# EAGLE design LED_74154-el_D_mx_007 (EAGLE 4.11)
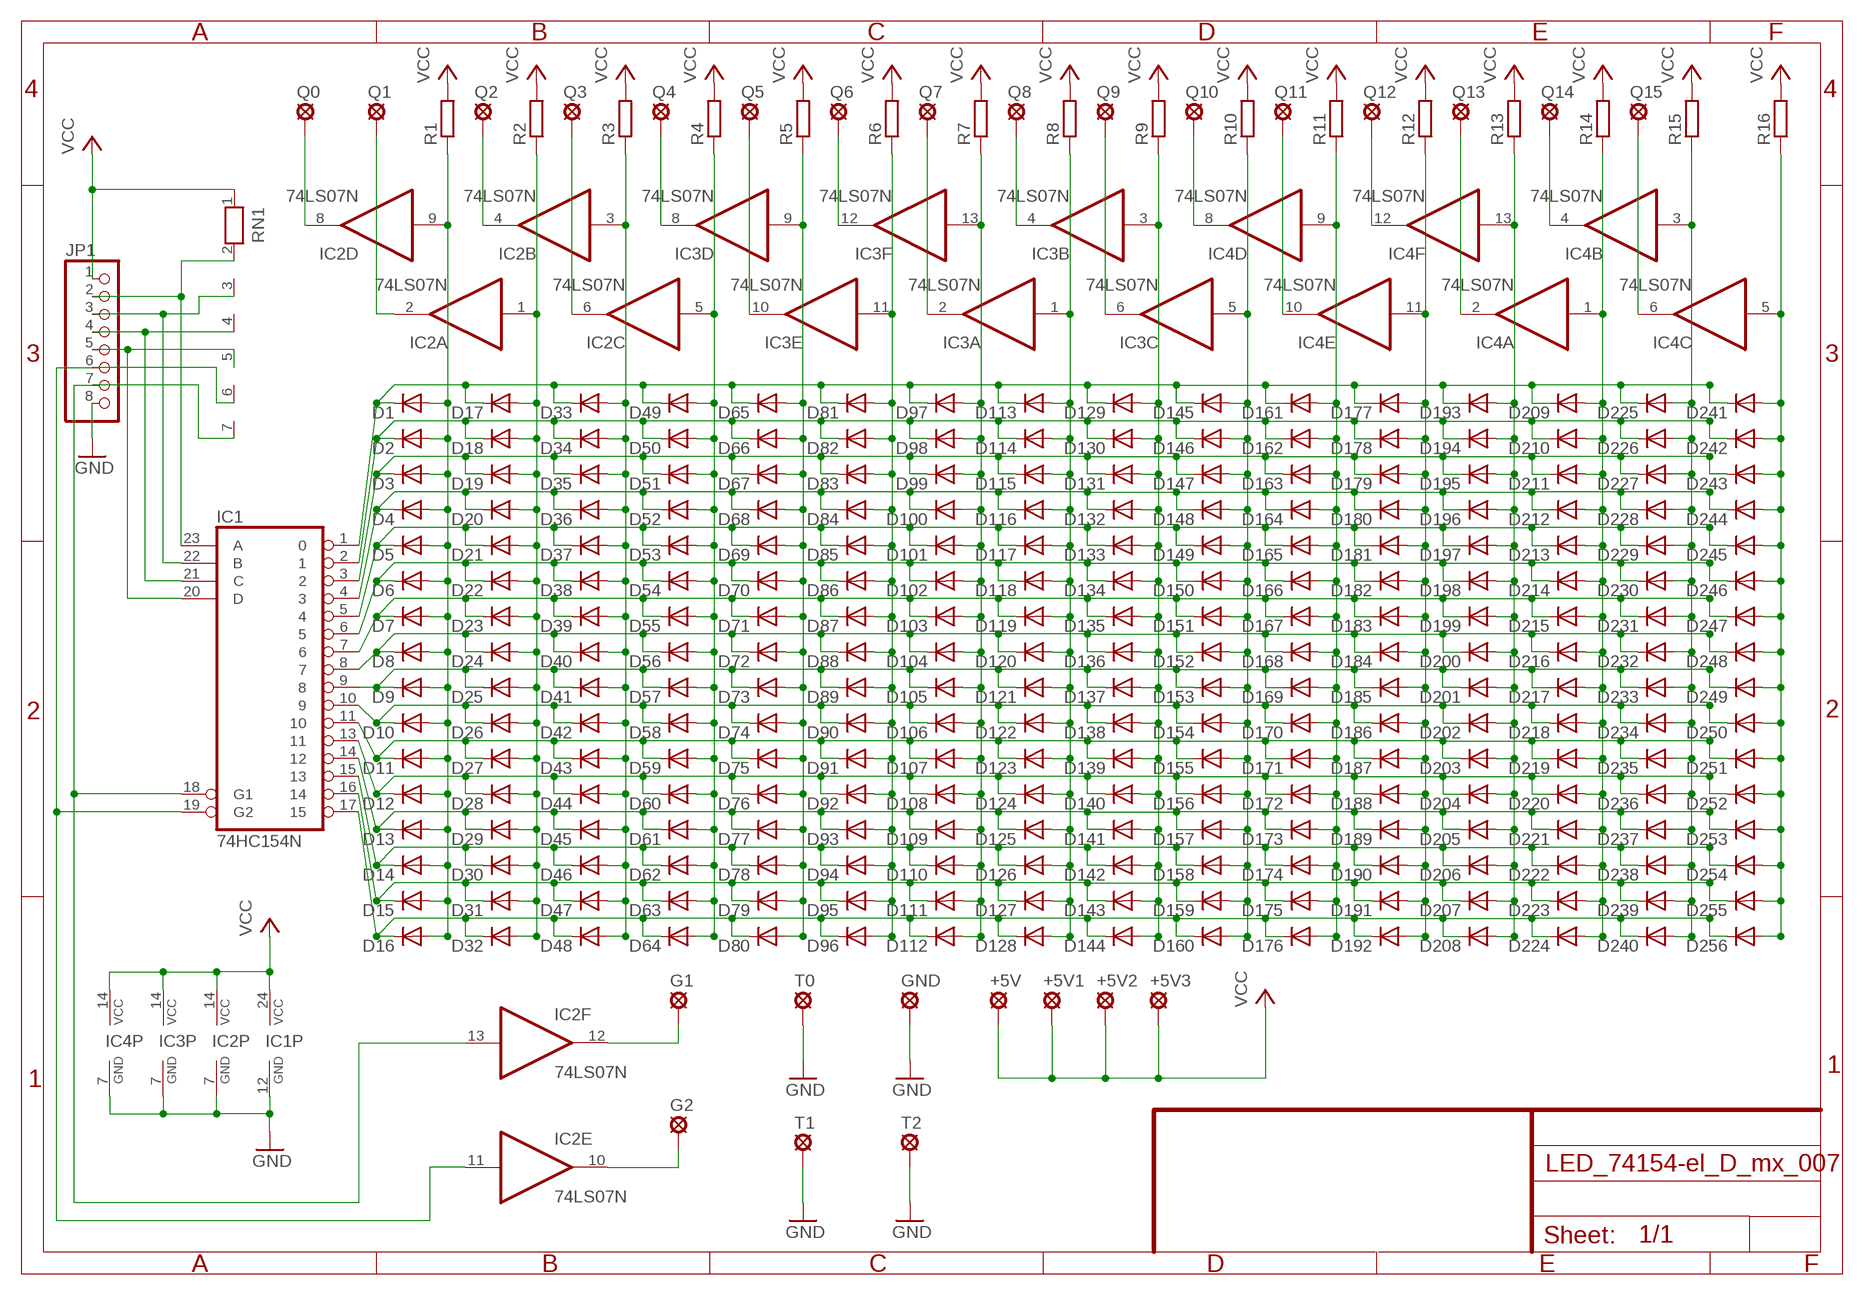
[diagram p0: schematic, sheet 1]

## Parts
+5V  SE11  [SE11]
+5V1  SE11  [SE11]
+5V2  SE11  [SE11]
+5V3  SE11  [SE11]
D1  DIODE-D-2.5  [D-2.5]
D2  DIODE-D-2.5  [D-2.5]
D3  DIODE-D-2.5  [D-2.5]
D4  DIODE-D-2.5  [D-2.5]
D5  DIODE-D-2.5  [D-2.5]
D6  DIODE-D-2.5  [D-2.5]
D7  DIODE-D-2.5  [D-2.5]
D8  DIODE-D-2.5  [D-2.5]
D9  DIODE-D-2.5  [D-2.5]
D10  DIODE-D-2.5  [D-2.5]
D11  DIODE-D-2.5  [D-2.5]
D12  DIODE-D-2.5  [D-2.5]
D13  DIODE-D-2.5  [D-2.5]
D14  DIODE-D-2.5  [D-2.5]
D15  DIODE-D-2.5  [D-2.5]
D16  DIODE-D-2.5  [D-2.5]
D17  DIODE-D-2.5  [D-2.5]
D18  DIODE-D-2.5  [D-2.5]
D19  DIODE-D-2.5  [D-2.5]
D20  DIODE-D-2.5  [D-2.5]
D21  DIODE-D-2.5  [D-2.5]
D22  DIODE-D-2.5  [D-2.5]
D23  DIODE-D-2.5  [D-2.5]
D24  DIODE-D-2.5  [D-2.5]
D25  DIODE-D-2.5  [D-2.5]
D26  DIODE-D-2.5  [D-2.5]
D27  DIODE-D-2.5  [D-2.5]
D28  DIODE-D-2.5  [D-2.5]
D29  DIODE-D-2.5  [D-2.5]
D30  DIODE-D-2.5  [D-2.5]
D31  DIODE-D-2.5  [D-2.5]
D32  DIODE-D-2.5  [D-2.5]
D33  DIODE-D-2.5  [D-2.5]
D34  DIODE-D-2.5  [D-2.5]
D35  DIODE-D-2.5  [D-2.5]
D36  DIODE-D-2.5  [D-2.5]
D37  DIODE-D-2.5  [D-2.5]
D38  DIODE-D-2.5  [D-2.5]
D39  DIODE-D-2.5  [D-2.5]
D40  DIODE-D-2.5  [D-2.5]
D41  DIODE-D-2.5  [D-2.5]
D42  DIODE-D-2.5  [D-2.5]
D43  DIODE-D-2.5  [D-2.5]
D44  DIODE-D-2.5  [D-2.5]
D45  DIODE-D-2.5  [D-2.5]
D46  DIODE-D-2.5  [D-2.5]
D47  DIODE-D-2.5  [D-2.5]
D48  DIODE-D-2.5  [D-2.5]
D49  DIODE-D-2.5  [D-2.5]
D50  DIODE-D-2.5  [D-2.5]
D51  DIODE-D-2.5  [D-2.5]
D52  DIODE-D-2.5  [D-2.5]
D53  DIODE-D-2.5  [D-2.5]
D54  DIODE-D-2.5  [D-2.5]
D55  DIODE-D-2.5  [D-2.5]
D56  DIODE-D-2.5  [D-2.5]
D57  DIODE-D-2.5  [D-2.5]
D58  DIODE-D-2.5  [D-2.5]
D59  DIODE-D-2.5  [D-2.5]
D60  DIODE-D-2.5  [D-2.5]
D61  DIODE-D-2.5  [D-2.5]
D62  DIODE-D-2.5  [D-2.5]
D63  DIODE-D-2.5  [D-2.5]
D64  DIODE-D-2.5  [D-2.5]
D65  DIODE-D-2.5  [D-2.5]
D66  DIODE-D-2.5  [D-2.5]
D67  DIODE-D-2.5  [D-2.5]
D68  DIODE-D-2.5  [D-2.5]
D69  DIODE-D-2.5  [D-2.5]
D70  DIODE-D-2.5  [D-2.5]
D71  DIODE-D-2.5  [D-2.5]
D72  DIODE-D-2.5  [D-2.5]
D73  DIODE-D-2.5  [D-2.5]
D74  DIODE-D-2.5  [D-2.5]
D75  DIODE-D-2.5  [D-2.5]
D76  DIODE-D-2.5  [D-2.5]
D77  DIODE-D-2.5  [D-2.5]
D78  DIODE-D-2.5  [D-2.5]
D79  DIODE-D-2.5  [D-2.5]
D80  DIODE-D-2.5  [D-2.5]
D81  DIODE-D-2.5  [D-2.5]
D82  DIODE-D-2.5  [D-2.5]
D83  DIODE-D-2.5  [D-2.5]
D84  DIODE-D-2.5  [D-2.5]
D85  DIODE-D-2.5  [D-2.5]
D86  DIODE-D-2.5  [D-2.5]
D87  DIODE-D-2.5  [D-2.5]
D88  DIODE-D-2.5  [D-2.5]
D89  DIODE-D-2.5  [D-2.5]
D90  DIODE-D-2.5  [D-2.5]
D91  DIODE-D-2.5  [D-2.5]
D92  DIODE-D-2.5  [D-2.5]
D93  DIODE-D-2.5  [D-2.5]
D94  DIODE-D-2.5  [D-2.5]
D95  DIODE-D-2.5  [D-2.5]
D96  DIODE-D-2.5  [D-2.5]
D97  DIODE-D-2.5  [D-2.5]
D98  DIODE-D-2.5  [D-2.5]
D99  DIODE-D-2.5  [D-2.5]
D100  DIODE-D-2.5  [D-2.5]
D101  DIODE-D-2.5  [D-2.5]
D102  DIODE-D-2.5  [D-2.5]
D103  DIODE-D-2.5  [D-2.5]
D104  DIODE-D-2.5  [D-2.5]
D105  DIODE-D-2.5  [D-2.5]
D106  DIODE-D-2.5  [D-2.5]
D107  DIODE-D-2.5  [D-2.5]
D108  DIODE-D-2.5  [D-2.5]
D109  DIODE-D-2.5  [D-2.5]
D110  DIODE-D-2.5  [D-2.5]
D111  DIODE-D-2.5  [D-2.5]
D112  DIODE-D-2.5  [D-2.5]
D113  DIODE-D-2.5  [D-2.5]
D114  DIODE-D-2.5  [D-2.5]
D115  DIODE-D-2.5  [D-2.5]
D116  DIODE-D-2.5  [D-2.5]
D117  DIODE-D-2.5  [D-2.5]
D118  DIODE-D-2.5  [D-2.5]
D119  DIODE-D-2.5  [D-2.5]
D120  DIODE-D-2.5  [D-2.5]
D121  DIODE-D-2.5  [D-2.5]
D122  DIODE-D-2.5  [D-2.5]
D123  DIODE-D-2.5  [D-2.5]
D124  DIODE-D-2.5  [D-2.5]
D125  DIODE-D-2.5  [D-2.5]
D126  DIODE-D-2.5  [D-2.5]
D127  DIODE-D-2.5  [D-2.5]
D128  DIODE-D-2.5  [D-2.5]
D129  DIODE-D-2.5  [D-2.5]
D130  DIODE-D-2.5  [D-2.5]
D131  DIODE-D-2.5  [D-2.5]
D132  DIODE-D-2.5  [D-2.5]
D133  DIODE-D-2.5  [D-2.5]
D134  DIODE-D-2.5  [D-2.5]
D135  DIODE-D-2.5  [D-2.5]
D136  DIODE-D-2.5  [D-2.5]
D137  DIODE-D-2.5  [D-2.5]
D138  DIODE-D-2.5  [D-2.5]
D139  DIODE-D-2.5  [D-2.5]
D140  DIODE-D-2.5  [D-2.5]
D141  DIODE-D-2.5  [D-2.5]
D142  DIODE-D-2.5  [D-2.5]
D143  DIODE-D-2.5  [D-2.5]
D144  DIODE-D-2.5  [D-2.5]
D145  DIODE-D-2.5  [D-2.5]
D146  DIODE-D-2.5  [D-2.5]
D147  DIODE-D-2.5  [D-2.5]
D148  DIODE-D-2.5  [D-2.5]
D149  DIODE-D-2.5  [D-2.5]
D150  DIODE-D-2.5  [D-2.5]
D151  DIODE-D-2.5  [D-2.5]
D152  DIODE-D-2.5  [D-2.5]
D153  DIODE-D-2.5  [D-2.5]
D154  DIODE-D-2.5  [D-2.5]
D155  DIODE-D-2.5  [D-2.5]
D156  DIODE-D-2.5  [D-2.5]
D157  DIODE-D-2.5  [D-2.5]
D158  DIODE-D-2.5  [D-2.5]
D159  DIODE-D-2.5  [D-2.5]
D160  DIODE-D-2.5  [D-2.5]
D161  DIODE-D-2.5  [D-2.5]
D162  DIODE-D-2.5  [D-2.5]
D163  DIODE-D-2.5  [D-2.5]
D164  DIODE-D-2.5  [D-2.5]
D165  DIODE-D-2.5  [D-2.5]
D166  DIODE-D-2.5  [D-2.5]
D167  DIODE-D-2.5  [D-2.5]
D168  DIODE-D-2.5  [D-2.5]
D169  DIODE-D-2.5  [D-2.5]
D170  DIODE-D-2.5  [D-2.5]
D171  DIODE-D-2.5  [D-2.5]
D172  DIODE-D-2.5  [D-2.5]
D173  DIODE-D-2.5  [D-2.5]
D174  DIODE-D-2.5  [D-2.5]
D175  DIODE-D-2.5  [D-2.5]
D176  DIODE-D-2.5  [D-2.5]
D177  DIODE-D-2.5  [D-2.5]
D178  DIODE-D-2.5  [D-2.5]
D179  DIODE-D-2.5  [D-2.5]
D180  DIODE-D-2.5  [D-2.5]
D181  DIODE-D-2.5  [D-2.5]
D182  DIODE-D-2.5  [D-2.5]
D183  DIODE-D-2.5  [D-2.5]
D184  DIODE-D-2.5  [D-2.5]
D185  DIODE-D-2.5  [D-2.5]
D186  DIODE-D-2.5  [D-2.5]
D187  DIODE-D-2.5  [D-2.5]
D188  DIODE-D-2.5  [D-2.5]
D189  DIODE-D-2.5  [D-2.5]
D190  DIODE-D-2.5  [D-2.5]
D191  DIODE-D-2.5  [D-2.5]
D192  DIODE-D-2.5  [D-2.5]
D193  DIODE-D-2.5  [D-2.5]
D194  DIODE-D-2.5  [D-2.5]
D195  DIODE-D-2.5  [D-2.5]
D196  DIODE-D-2.5  [D-2.5]
D197  DIODE-D-2.5  [D-2.5]
D198  DIODE-D-2.5  [D-2.5]
D199  DIODE-D-2.5  [D-2.5]
D200  DIODE-D-2.5  [D-2.5]
D201  DIODE-D-2.5  [D-2.5]
D202  DIODE-D-2.5  [D-2.5]
D203  DIODE-D-2.5  [D-2.5]
D204  DIODE-D-2.5  [D-2.5]
D205  DIODE-D-2.5  [D-2.5]
D206  DIODE-D-2.5  [D-2.5]
D207  DIODE-D-2.5  [D-2.5]
D208  DIODE-D-2.5  [D-2.5]
D209  DIODE-D-2.5  [D-2.5]
D210  DIODE-D-2.5  [D-2.5]
D211  DIODE-D-2.5  [D-2.5]
D212  DIODE-D-2.5  [D-2.5]
D213  DIODE-D-2.5  [D-2.5]
D214  DIODE-D-2.5  [D-2.5]
D215  DIODE-D-2.5  [D-2.5]
D216  DIODE-D-2.5  [D-2.5]
D217  DIODE-D-2.5  [D-2.5]
D218  DIODE-D-2.5  [D-2.5]
D219  DIODE-D-2.5  [D-2.5]
D220  DIODE-D-2.5  [D-2.5]
D221  DIODE-D-2.5  [D-2.5]
D222  DIODE-D-2.5  [D-2.5]
D223  DIODE-D-2.5  [D-2.5]
D224  DIODE-D-2.5  [D-2.5]
D225  DIODE-D-2.5  [D-2.5]
D226  DIODE-D-2.5  [D-2.5]
D227  DIODE-D-2.5  [D-2.5]
D228  DIODE-D-2.5  [D-2.5]
D229  DIODE-D-2.5  [D-2.5]
D230  DIODE-D-2.5  [D-2.5]
D231  DIODE-D-2.5  [D-2.5]
D232  DIODE-D-2.5  [D-2.5]
D233  DIODE-D-2.5  [D-2.5]
D234  DIODE-D-2.5  [D-2.5]
D235  DIODE-D-2.5  [D-2.5]
D236  DIODE-D-2.5  [D-2.5]
D237  DIODE-D-2.5  [D-2.5]
D238  DIODE-D-2.5  [D-2.5]
D239  DIODE-D-2.5  [D-2.5]
D240  DIODE-D-2.5  [D-2.5]
D241  DIODE-D-2.5  [D-2.5]
D242  DIODE-D-2.5  [D-2.5]
D243  DIODE-D-2.5  [D-2.5]
D244  DIODE-D-2.5  [D-2.5]
D245  DIODE-D-2.5  [D-2.5]
D246  DIODE-D-2.5  [D-2.5]
D247  DIODE-D-2.5  [D-2.5]
D248  DIODE-D-2.5  [D-2.5]
D249  DIODE-D-2.5  [D-2.5]
D250  DIODE-D-2.5  [D-2.5]
D251  DIODE-D-2.5  [D-2.5]
D252  DIODE-D-2.5  [D-2.5]
D253  DIODE-D-2.5  [D-2.5]
D254  DIODE-D-2.5  [D-2.5]
D255  DIODE-D-2.5  [D-2.5]
D256  DIODE-D-2.5  [D-2.5]
G1  SE11  [SE11]
G2  SE11  [SE11]
GND  SE11  [SE11]
IC1  74HC154N  [DIL24-6]
IC2  74LS07N  [DIL14]
IC3  74LS07N  [DIL14]
IC4  74LS07N  [DIL14]
JP1  PINHD-1X8  [1X08]
Q0  SE11  [SE11]
Q1  SE11  [SE11]
Q2  SE11  [SE11]
Q3  SE11  [SE11]
Q4  SE11  [SE11]
Q5  SE11  [SE11]
Q6  SE11  [SE11]
Q7  SE11  [SE11]
Q8  SE11  [SE11]
Q9  SE11  [SE11]
Q10  SE11  [SE11]
Q11  SE11  [SE11]
Q12  SE11  [SE11]
Q13  SE11  [SE11]
Q14  SE11  [SE11]
Q15  SE11  [SE11]
R1  R-EU_0204/5  [0204/5]
R2  R-EU_0204/5  [0204/5]
R3  R-EU_0204/5  [0204/5]
R4  R-EU_0204/5  [0204/5]
R5  R-EU_0204/5  [0204/5]
R6  R-EU_0204/5  [0204/5]
R7  R-EU_0204/5  [0204/5]
R8  R-EU_0204/5  [0204/5]
R9  R-EU_0204/5  [0204/5]
R10  R-EU_0204/5  [0204/5]
R11  R-EU_0204/5  [0204/5]
R12  R-EU_0204/5  [0204/5]
R13  R-EU_0204/5  [0204/5]
R14  R-EU_0204/5  [0204/5]
R15  R-EU_0204/5  [0204/5]
R16  R-EU_0204/5  [0204/5]
RN1  RN06  [RN-7]
T0  SE11  [SE11]
T1  SE11  [SE11]
T2  SE11  [SE11]

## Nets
GND: GND.MP IC1.12(GND) IC2.7(P:GND) IC3.7(P:GND) IC4.7(P:GND) JP1.8 T0.MP T1.MP T2.MP
N$1: D225.A D226.A D227.A D228.A D229.A D230.A D231.A D232.A D233.A D234.A D235.A D236.A D237.A D238.A D239.A D240.A IC4.3(B:I) R15.1
N$2: D2.C D18.C D34.C D50.C D66.C D82.C D98.C D114.C D130.C D146.C D162.C D178.C D194.C D210.C D226.C D242.C IC1.2
N$3: D33.A D34.A D35.A D36.A D37.A D38.A D39.A D40.A D41.A D42.A D43.A D44.A D45.A D46.A D47.A D48.A IC2.3(B:I) R3.1
N$4: D4.C D20.C D36.C D52.C D68.C D84.C D100.C D116.C D132.C D148.C D164.C D180.C D196.C D212.C D228.C D244.C IC1.4
N$5: D5.C D21.C D37.C D53.C D69.C D85.C D101.C D117.C D133.C D149.C D165.C D181.C D197.C D213.C D229.C D245.C IC1.5
N$6: D6.C D22.C D38.C D54.C D70.C D86.C D102.C D118.C D134.C D150.C D166.C D182.C D198.C D214.C D230.C D246.C IC1.6
N$7: D7.C D23.C D39.C D55.C D71.C D87.C D103.C D119.C D135.C D151.C D167.C D183.C D199.C D215.C D231.C D247.C IC1.7
N$8: D8.C D24.C D40.C D56.C D72.C D88.C D104.C D120.C D136.C D152.C D168.C D184.C D200.C D216.C D232.C D248.C IC1.8
N$9: D9.C D25.C D41.C D57.C D73.C D89.C D105.C D121.C D137.C D153.C D169.C D185.C D201.C D217.C D233.C D249.C IC1.9
N$10: D10.C D26.C D42.C D58.C D74.C D90.C D106.C D122.C D138.C D154.C D170.C D186.C D202.C D218.C D234.C D250.C IC1.10
N$11: D11.C D27.C D43.C D59.C D75.C D91.C D107.C D123.C D139.C D155.C D171.C D187.C D203.C D219.C D235.C D251.C IC1.11
N$12: D12.C D28.C D44.C D60.C D76.C D92.C D108.C D124.C D140.C D156.C D172.C D188.C D204.C D220.C D236.C D252.C IC1.13
N$13: D13.C D29.C D45.C D61.C D77.C D93.C D109.C D125.C D141.C D157.C D173.C D189.C D205.C D221.C D237.C D253.C IC1.14
N$14: D14.C D30.C D46.C D62.C D78.C D94.C D110.C D126.C D142.C D158.C D174.C D190.C D206.C D222.C D238.C D254.C IC1.15
N$15: D15.C D31.C D47.C D63.C D79.C D95.C D111.C D127.C D143.C D159.C D175.C D191.C D207.C D223.C D239.C D255.C IC1.16
N$16: D16.C D32.C D48.C D64.C D80.C D96.C D112.C D128.C D144.C D160.C D176.C D192.C D208.C D224.C D240.C D256.C IC1.17
N$17: D49.A D50.A D51.A D52.A D53.A D54.A D55.A D56.A D57.A D58.A D59.A D60.A D61.A D62.A D63.A D64.A IC2.5(C:I) R4.1
N$18: D65.A D66.A D67.A D68.A D69.A D70.A D71.A D72.A D73.A D74.A D75.A D76.A D77.A D78.A D79.A D80.A IC3.9(D:I) R5.1
N$19: D81.A D82.A D83.A D84.A D85.A D86.A D87.A D88.A D89.A D90.A D91.A D92.A D93.A D94.A D95.A D96.A IC3.11(E:I) R6.1
N$20: D97.A D98.A D99.A D100.A D101.A D102.A D103.A D104.A D105.A D106.A D107.A D108.A D109.A D110.A D111.A D112.A IC3.13(F:I) R7.1
N$21: D3.C D19.C D35.C D51.C D67.C D83.C D99.C D115.C D131.C D147.C D163.C D179.C D195.C D211.C D227.C D243.C IC1.3
N$22: IC1.19(G2) IC2.11(E:I) JP1.6 RN1.6
N$23: IC1.18(G1) IC2.13(F:I) JP1.7 RN1.7
N$24: D145.A D146.A D147.A D148.A D149.A D150.A D151.A D152.A D153.A D154.A D155.A D156.A D157.A D158.A D159.A D160.A IC3.5(C:I) R10.1
N$25: D193.A D194.A D195.A D196.A D197.A D198.A D199.A D200.A D201.A D202.A D203.A D204.A D205.A D206.A D207.A D208.A IC4.13(F:I) R13.1
N$26: IC1.23(A) JP1.2 RN1.2
N$27: IC1.22(B) JP1.3 RN1.3
N$28: IC1.21(C) JP1.4 RN1.4
N$29: D1.A D2.A D3.A D4.A D5.A D6.A D7.A D8.A D9.A D10.A D11.A D12.A D13.A D14.A D15.A D16.A IC2.9(D:I) R1.1
N$30: D17.A D18.A D19.A D20.A D21.A D22.A D23.A D24.A D25.A D26.A D27.A D28.A D29.A D30.A D31.A D32.A IC2.1(A:I) R2.1
N$31: IC1.20(D) JP1.5 RN1.5
N$32: D113.A D114.A D115.A D116.A D117.A D118.A D119.A D120.A D121.A D122.A D123.A D124.A D125.A D126.A D127.A D128.A IC3.1(A:I) R8.1
N$33: D129.A D130.A D131.A D132.A D133.A D134.A D135.A D136.A D137.A D138.A D139.A D140.A D141.A D142.A D143.A D144.A IC3.3(B:I) R9.1
N$34: D241.A D242.A D243.A D244.A D245.A D246.A D247.A D248.A D249.A D250.A D251.A D252.A D253.A D254.A D255.A D256.A IC4.5(C:I) R16.1
N$39: D209.A D210.A D211.A D212.A D213.A D214.A D215.A D216.A D217.A D218.A D219.A D220.A D221.A D222.A D223.A D224.A IC4.1(A:I) R14.1
N$41: D161.A D162.A D163.A D164.A D165.A D166.A D167.A D168.A D169.A D170.A D171.A D172.A D173.A D174.A D175.A D176.A IC4.9(D:I) R11.1
N$42: D1.C D17.C D33.C D49.C D65.C D81.C D97.C D113.C D129.C D145.C D161.C D177.C D193.C D209.C D225.C D241.C IC1.1
N$50: D177.A D178.A D179.A D180.A D181.A D182.A D183.A D184.A D185.A D186.A D187.A D188.A D189.A D190.A D191.A D192.A IC4.11(E:I) R12.1
N$51: G1.MP IC2.12(F:O)
N$52: IC2.8(D:O) Q0.MP
N$53: IC2.2(A:O) Q1.MP
N$54: IC2.4(B:O) Q2.MP
N$55: IC2.6(C:O) Q3.MP
N$56: IC3.8(D:O) Q4.MP
N$57: IC3.10(E:O) Q5.MP
N$58: IC3.12(F:O) Q6.MP
N$59: IC3.2(A:O) Q7.MP
N$60: IC3.4(B:O) Q8.MP
N$61: IC3.6(C:O) Q9.MP
N$62: IC4.8(D:O) Q10.MP
N$63: IC4.10(E:O) Q11.MP
N$64: IC4.12(F:O) Q12.MP
N$65: IC4.2(A:O) Q13.MP
N$66: IC4.4(B:O) Q14.MP
N$67: IC4.6(C:O) Q15.MP
N$68: G2.MP IC2.10(E:O)
VCC: +5V1.MP +5V2.MP +5V3.MP +5V.MP IC1.24(VCC) IC2.14(P:VCC) IC3.14(P:VCC) IC4.14(P:VCC) JP1.1 R1.2 R2.2 R3.2 R4.2 R5.2 R6.2 R7.2 R8.2 R9.2 R10.2 R11.2 R12.2 R13.2 R14.2 R15.2 R16.2 RN1.1

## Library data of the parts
+5V +5V1-+5V3 G1 G2 GND Q0 Q1-Q15 T0 T1 T2 = solpad:SE11: SOLDER PAD
D1-D256 = diode:DIODE-: DIODE
IC1 = 74xx-eu:74*154: 4-line to 16-line data SELECTOR/MULTIPLEXER
IC2-IC4 = 74xx-eu:74*07: Hex BUFFER, open collector high-voltage output
JP1 = pinhead:PINHD-1X8: PIN HEADER
R1-R16 = rcl:R-EU_: RESISTOR, European symbol
RN1 = resistor-net:RN06: RESISTOR NETWORK

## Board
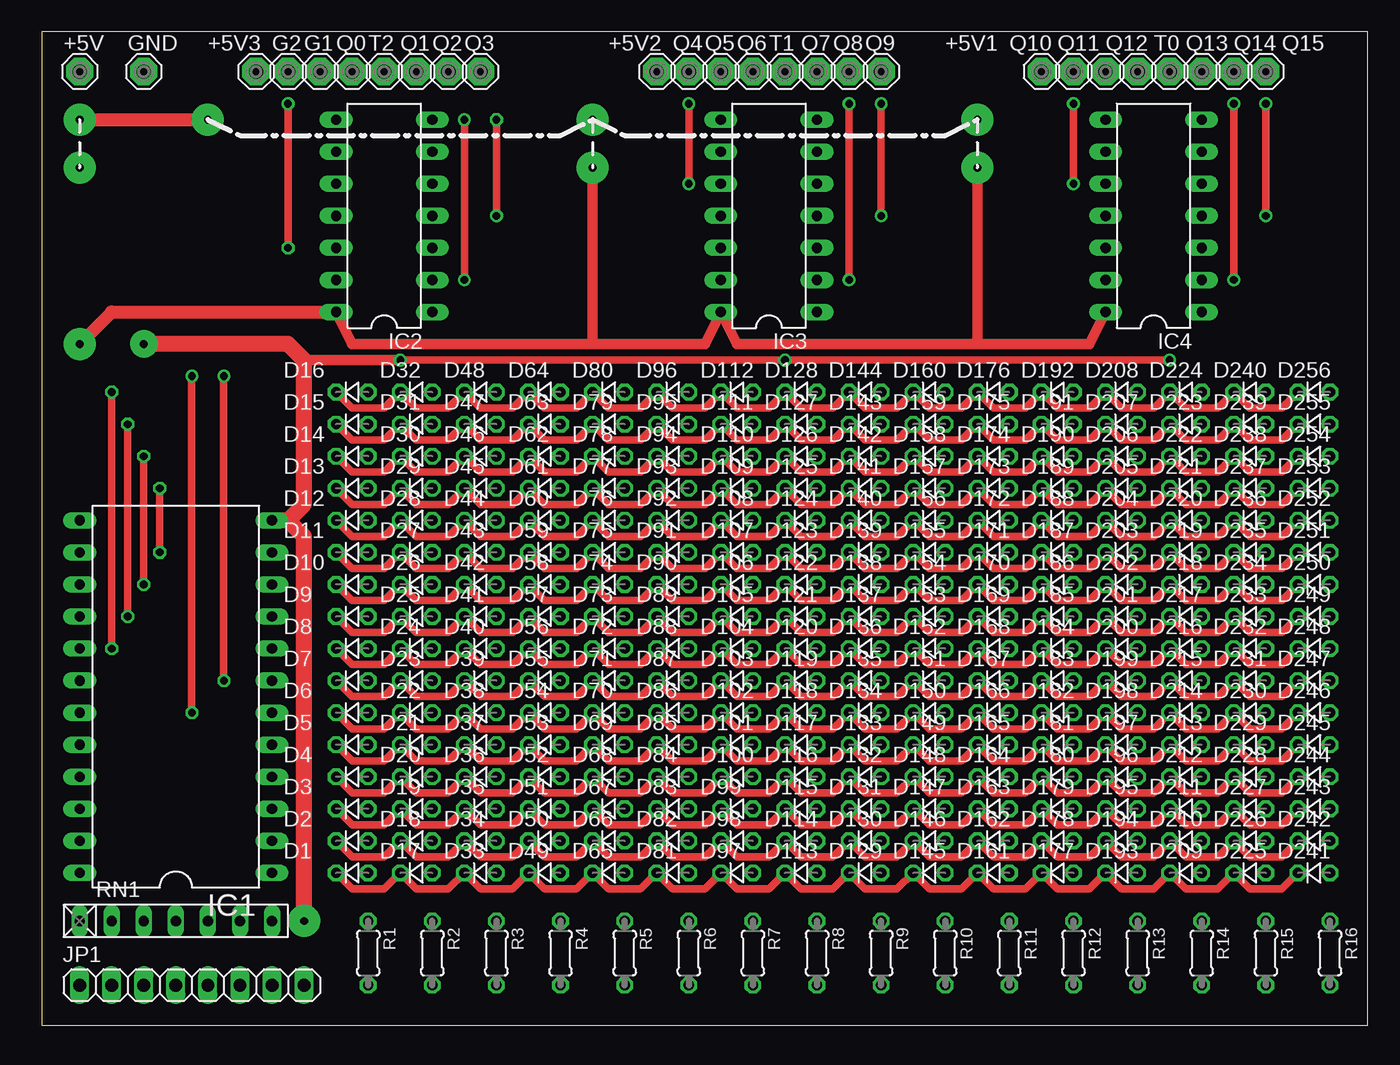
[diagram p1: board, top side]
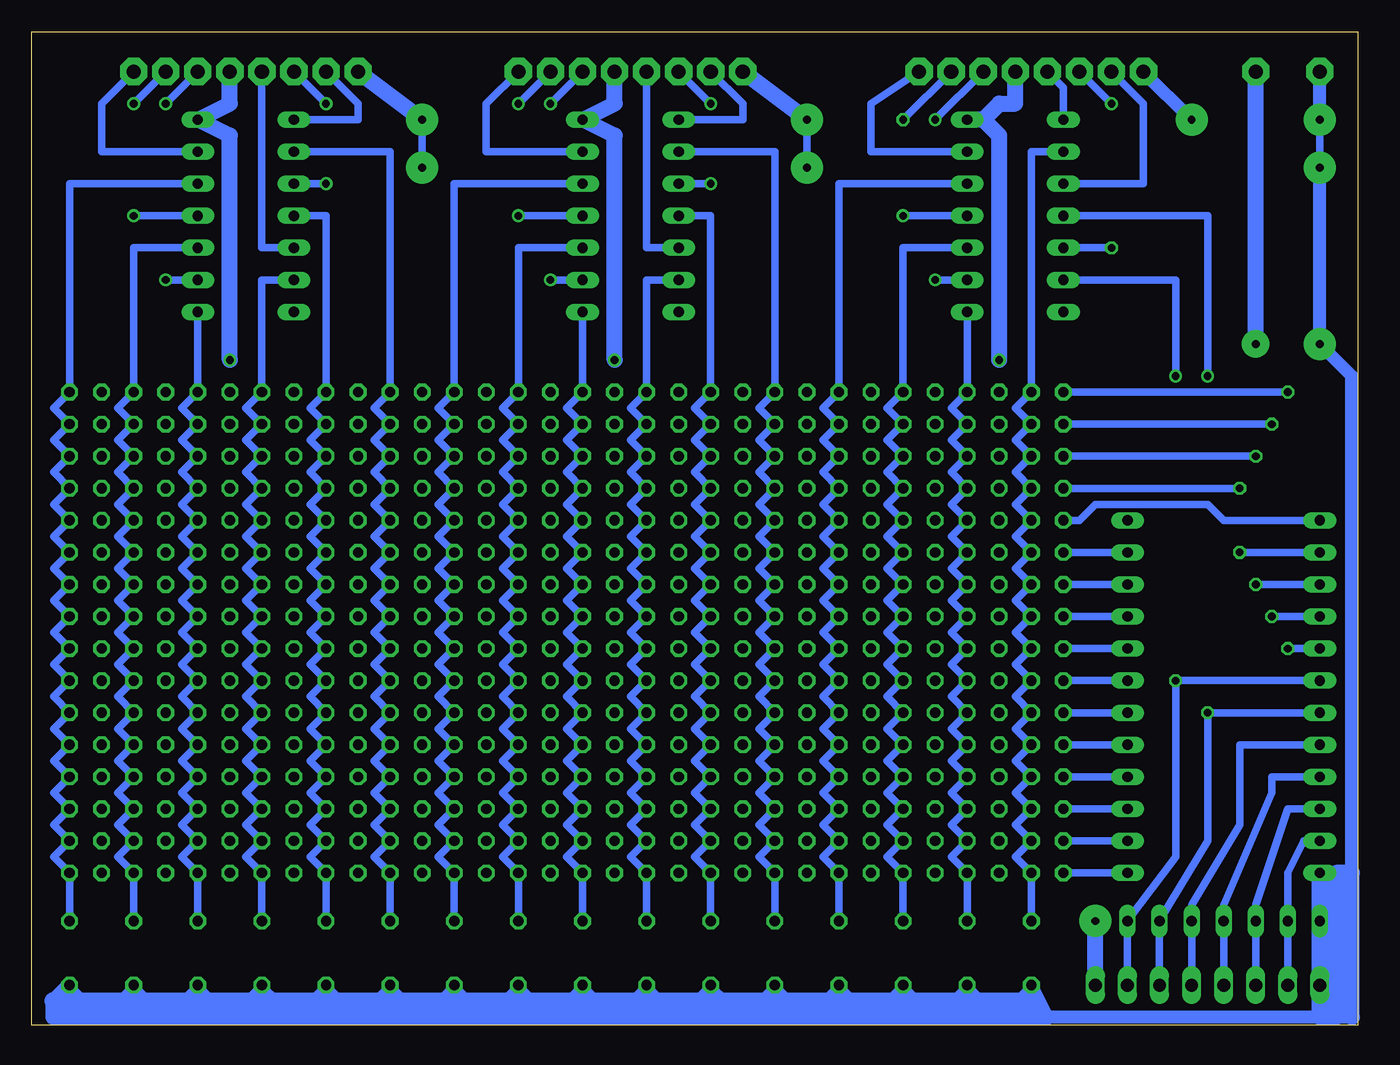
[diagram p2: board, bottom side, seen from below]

Size 105.08 x 78.73 mm. Coordinates in mm from the lower left corner, seen from the top.
Outline: 0,0 105.08,0 105.08,78.73 0,78.73 0,0
Copper layers (1*16): Top 0.035mm / dielectric 1.5mm / Bottom 0.035mm
Design rules "default": minimum track width 10mil, minimum drill 24mil, track to track 8mil, track to pad 8mil, pad to pad 8mil, via to via 8mil, smd to smd 8mil, copper to edge 40mil, drill to drill 8mil, minimum pad ring 10mil, minimum via ring 8mil, stop-mask expansion 4mil, vias tented up to drill 0mil, thermal gap 10mil

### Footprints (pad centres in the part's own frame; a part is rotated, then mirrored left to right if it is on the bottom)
SE11 = drill 1.118 pad 2.159 octagon: MP 0,0
D-2.5 = drill 0.813 octagon: A 1.27,0; C -1.27,0
DIL24-6 = drill 0.813 long: 1 -13.97,-7.62; 2 -11.43,-7.62; 3 -8.89,-7.62; 4 -6.35,-7.62; 5 -3.81,-7.62; 6 -1.27,-7.62; 7 1.27,-7.62; 8 3.81,-7.62; 9 6.35,-7.62; 10 8.89,-7.62; 11 11.43,-7.62; 12 13.97,-7.62; 13 13.97,7.62; 14 11.43,7.62; 15 8.89,7.62; 16 6.35,7.62; 17 3.81,7.62; 18 1.27,7.62; 19 -1.27,7.62; 20 -3.81,7.62; 21 -6.35,7.62; 22 -8.89,7.62; 23 -11.43,7.62; 24 -13.97,7.62
DIL14 = drill 0.813 long: 1 -7.62,-3.81; 2 -5.08,-3.81; 3 -2.54,-3.81; 4 0,-3.81; 5 2.54,-3.81; 6 5.08,-3.81; 7 7.62,-3.81; 8 7.62,3.81; 9 5.08,3.81; 10 2.54,3.81; 11 0,3.81; 12 -2.54,3.81; 13 -5.08,3.81; 14 -7.62,3.81
1X08 = drill 1.016 long: 1 -8.89,0; 2 -6.35,0; 3 -3.81,0; 4 -1.27,0; 5 1.27,0; 6 3.81,0; 7 6.35,0; 8 8.89,0
0204/5 = drill 0.813 octagon: 1 -2.54,0; 2 2.54,0
RN-7 = drill 0.813 long: 1 -7.62,0; 2 -5.08,0; 3 -2.54,0; 4 0,0; 5 2.54,0; 6 5.08,0; 7 7.62,0

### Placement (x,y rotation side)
+5V  3.01,75.56 0 top
+5V1  79.21,75.56 0 top
+5V2  48.73,75.56 0 top
+5V3  16.98,75.56 0 top
D1  24.6,12.06 0 top
D2  24.6,14.6 0 top
D3  24.6,17.14 0 top
D4  24.6,19.68 0 top
D5  24.6,22.22 0 top
D6  24.6,24.76 0 top
D7  24.6,27.3 0 top
D8  24.6,29.84 0 top
D9  24.6,32.38 0 top
D10  24.6,34.92 0 top
D11  24.6,37.46 0 top
D12  24.6,40 0 top
D13  24.6,42.54 0 top
D14  24.6,45.08 0 top
D15  24.6,47.62 0 top
D16  24.6,50.16 0 top
D17  29.68,12.06 0 top
D18  29.68,14.6 0 top
D19  29.68,17.14 0 top
D20  29.68,19.68 0 top
D21  29.68,22.22 0 top
D22  29.68,24.76 0 top
D23  29.68,27.3 0 top
D24  29.68,29.84 0 top
D25  29.68,32.38 0 top
D26  29.68,34.92 0 top
D27  29.68,37.46 0 top
D28  29.68,40 0 top
D29  29.68,42.54 0 top
D30  29.68,45.08 0 top
D31  29.68,47.62 0 top
D32  29.68,50.16 0 top
D33  34.76,12.06 0 top
D34  34.76,14.6 0 top
D35  34.76,17.14 0 top
D36  34.76,19.68 0 top
D37  34.76,22.22 0 top
D38  34.76,24.76 0 top
D39  34.76,27.3 0 top
D40  34.76,29.84 0 top
D41  34.76,32.38 0 top
D42  34.76,34.92 0 top
D43  34.76,37.46 0 top
D44  34.76,40 0 top
D45  34.76,42.54 0 top
D46  34.76,45.08 0 top
D47  34.76,47.62 0 top
D48  34.76,50.16 0 top
D49  39.84,12.06 0 top
D50  39.84,14.6 0 top
D51  39.84,17.14 0 top
D52  39.84,19.68 0 top
D53  39.84,22.22 0 top
D54  39.84,24.76 0 top
D55  39.84,27.3 0 top
D56  39.84,29.84 0 top
D57  39.84,32.38 0 top
D58  39.84,34.92 0 top
D59  39.84,37.46 0 top
D60  39.84,40 0 top
D61  39.84,42.54 0 top
D62  39.84,45.08 0 top
D63  39.84,47.62 0 top
D64  39.84,50.16 0 top
D65  44.92,12.06 0 top
D66  44.92,14.6 0 top
D67  44.92,17.14 0 top
D68  44.92,19.68 0 top
D69  44.92,22.22 0 top
D70  44.92,24.76 0 top
D71  44.92,27.3 0 top
D72  44.92,29.84 0 top
D73  44.92,32.38 0 top
D74  44.92,34.92 0 top
D75  44.92,37.46 0 top
D76  44.92,40 0 top
D77  44.92,42.54 0 top
D78  44.92,45.08 0 top
D79  44.92,47.62 0 top
D80  44.92,50.16 0 top
D81  50,12.06 0 top
D82  50,14.6 0 top
D83  50,17.14 0 top
D84  50,19.68 0 top
D85  50,22.22 0 top
D86  50,24.76 0 top
D87  50,27.3 0 top
D88  50,29.84 0 top
D89  50,32.38 0 top
D90  50,34.92 0 top
D91  50,37.46 0 top
D92  50,40 0 top
D93  50,42.54 0 top
D94  50,45.08 0 top
D95  50,47.62 0 top
D96  50,50.16 0 top
D97  55.08,12.06 0 top
D98  55.08,14.6 0 top
D99  55.08,17.14 0 top
D100  55.08,19.68 0 top
D101  55.08,22.22 0 top
D102  55.08,24.76 0 top
D103  55.08,27.3 0 top
D104  55.08,29.84 0 top
D105  55.08,32.38 0 top
D106  55.08,34.92 0 top
D107  55.08,37.46 0 top
D108  55.08,40 0 top
D109  55.08,42.54 0 top
D110  55.08,45.08 0 top
D111  55.08,47.62 0 top
D112  55.08,50.16 0 top
D113  60.16,12.06 0 top
D114  60.16,14.6 0 top
D115  60.16,17.14 0 top
D116  60.16,19.68 0 top
D117  60.16,22.22 0 top
D118  60.16,24.76 0 top
D119  60.16,27.3 0 top
D120  60.16,29.84 0 top
D121  60.16,32.38 0 top
D122  60.16,34.92 0 top
D123  60.16,37.46 0 top
D124  60.16,40 0 top
D125  60.16,42.54 0 top
D126  60.16,45.08 0 top
D127  60.16,47.62 0 top
D128  60.16,50.16 0 top
D129  65.24,12.06 0 top
D130  65.24,14.6 0 top
D131  65.24,17.14 0 top
D132  65.24,19.68 0 top
D133  65.24,22.22 0 top
D134  65.24,24.76 0 top
D135  65.24,27.3 0 top
D136  65.24,29.84 0 top
D137  65.24,32.38 0 top
D138  65.24,34.92 0 top
D139  65.24,37.46 0 top
D140  65.24,40 0 top
D141  65.24,42.54 0 top
D142  65.24,45.08 0 top
D143  65.24,47.62 0 top
D144  65.24,50.16 0 top
D145  70.32,12.06 0 top
D146  70.32,14.6 0 top
D147  70.32,17.14 0 top
D148  70.32,19.68 0 top
D149  70.32,22.22 0 top
D150  70.32,24.76 0 top
D151  70.32,27.3 0 top
D152  70.32,29.84 0 top
D153  70.32,32.38 0 top
D154  70.32,34.92 0 top
D155  70.32,37.46 0 top
D156  70.32,40 0 top
D157  70.32,42.54 0 top
D158  70.32,45.08 0 top
D159  70.32,47.62 0 top
D160  70.32,50.16 0 top
D161  75.4,12.06 0 top
D162  75.4,14.6 0 top
D163  75.4,17.14 0 top
D164  75.4,19.68 0 top
D165  75.4,22.22 0 top
D166  75.4,24.76 0 top
D167  75.4,27.3 0 top
D168  75.4,29.84 0 top
D169  75.4,32.38 0 top
D170  75.4,34.92 0 top
D171  75.4,37.46 0 top
D172  75.4,40 0 top
D173  75.4,42.54 0 top
D174  75.4,45.08 0 top
D175  75.4,47.62 0 top
D176  75.4,50.16 0 top
D177  80.48,12.06 0 top
D178  80.48,14.6 0 top
D179  80.48,17.14 0 top
D180  80.48,19.68 0 top
D181  80.48,22.22 0 top
D182  80.48,24.76 0 top
D183  80.48,27.3 0 top
D184  80.48,29.84 0 top
D185  80.48,32.38 0 top
D186  80.48,34.92 0 top
D187  80.48,37.46 0 top
D188  80.48,40 0 top
D189  80.48,42.54 0 top
D190  80.48,45.08 0 top
D191  80.48,47.62 0 top
D192  80.48,50.16 0 top
D193  85.56,12.06 0 top
D194  85.56,14.6 0 top
D195  85.56,17.14 0 top
D196  85.56,19.68 0 top
D197  85.56,22.22 0 top
D198  85.56,24.76 0 top
D199  85.56,27.3 0 top
D200  85.56,29.84 0 top
D201  85.56,32.38 0 top
D202  85.56,34.92 0 top
D203  85.56,37.46 0 top
D204  85.56,40 0 top
D205  85.56,42.54 0 top
D206  85.56,45.08 0 top
D207  85.56,47.62 0 top
D208  85.56,50.16 0 top
D209  90.64,12.06 0 top
D210  90.64,14.6 0 top
D211  90.64,17.14 0 top
D212  90.64,19.68 0 top
D213  90.64,22.22 0 top
D214  90.64,24.76 0 top
D215  90.64,27.3 0 top
D216  90.64,29.84 0 top
D217  90.64,32.38 0 top
D218  90.64,34.92 0 top
D219  90.64,37.46 0 top
D220  90.64,40 0 top
D221  90.64,42.54 0 top
D222  90.64,45.08 0 top
D223  90.64,47.62 0 top
D224  90.64,50.16 0 top
D225  95.72,12.06 0 top
D226  95.72,14.6 0 top
D227  95.72,17.14 0 top
D228  95.72,19.68 0 top
D229  95.72,22.22 0 top
D230  95.72,24.76 0 top
D231  95.72,27.3 0 top
D232  95.72,29.84 0 top
D233  95.72,32.38 0 top
D234  95.72,34.92 0 top
D235  95.72,37.46 0 top
D236  95.72,40 0 top
D237  95.72,42.54 0 top
D238  95.72,45.08 0 top
D239  95.72,47.62 0 top
D240  95.72,50.16 0 top
D241  100.8,12.06 0 top
D242  100.8,14.6 0 top
D243  100.8,17.14 0 top
D244  100.8,19.68 0 top
D245  100.8,22.22 0 top
D246  100.8,24.76 0 top
D247  100.8,27.3 0 top
D248  100.8,29.84 0 top
D249  100.8,32.38 0 top
D250  100.8,34.92 0 top
D251  100.8,37.46 0 top
D252  100.8,40 0 top
D253  100.8,42.54 0 top
D254  100.8,45.08 0 top
D255  100.8,47.62 0 top
D256  100.8,50.16 0 top
G1  22.06,75.56 0 top
G2  19.52,75.56 0 top
GND  8.09,75.56 0 top
IC1  10.63,26.03 90 top
IC2  27.14,64.13 90 top
IC3  57.62,64.13 90 top
IC4  88.1,64.13 90 top
JP1  11.9,3.17 0 top
Q0  24.6,75.56 0 top
Q1  29.68,75.56 0 top
Q2  32.22,75.56 0 top
Q3  34.76,75.56 0 top
Q4  51.27,75.56 0 top
Q5  53.81,75.56 0 top
Q6  56.35,75.56 0 top
Q7  61.43,75.56 0 top
Q8  63.97,75.56 0 top
Q9  66.51,75.56 0 top
Q10  81.75,75.56 0 top
Q11  84.29,75.56 0 top
Q12  86.83,75.56 0 top
Q13  91.91,75.56 0 top
Q14  94.45,75.56 0 top
Q15  96.99,75.56 0 top
R1  25.87,5.71 270 top
R2  30.95,5.71 270 top
R3  36.03,5.71 270 top
R4  41.11,5.71 270 top
R5  46.19,5.71 270 top
R6  51.27,5.71 270 top
R7  56.35,5.71 270 top
R8  61.43,5.71 270 top
R9  66.51,5.71 270 top
R10  71.59,5.71 270 top
R11  76.67,5.71 270 top
R12  81.75,5.71 270 top
R13  86.83,5.71 270 top
R14  91.91,5.71 270 top
R15  96.99,5.71 270 top
R16  102.07,5.71 270 top
RN1  10.63,8.25 0 top
T0  89.37,75.56 0 top
T1  58.89,75.56 0 top
T2  27.14,75.56 0 top

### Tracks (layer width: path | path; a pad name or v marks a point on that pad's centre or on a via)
GND  (via drill 0.61, 0.61 pad 2.54)
  Top 0.61: v89.37,52.7 v58.89,52.7 v28.41,52.7
  Top 0.813: 20.79,52.7 v28.41,52.7
  Top 1.27: v20.79,8.25 20.79,38.73 19.52,40 | 19.52,40 IC1.12 | 19.52,40 20.79,41.27 20.79,52.7 19.52,53.97 v8.09,53.97
  Bottom 1.27: JP1.8 v20.79,8.25 | v28.41,52.7 28.41,70.48 29.68,71.75 | 29.68,71.75 IC2.7 | 29.68,71.75 28.41,73.02 27.14,73.02 T2.MP | T1.MP 58.89,73.02 IC3.7 58.89,70.48 v58.89,52.7 | T0.MP 89.37,73.02 IC4.7 89.37,70.48 v89.37,52.7 | v8.09,53.97 GND.MP
N$1
  Bottom 0.61: R15.1 D225.A 98.26,13.33 D226.A 98.26,15.87 D227.A 98.26,18.41 D228.A 98.26,20.95 D229.A 98.26,23.49 D230.A 98.26,26.03 D231.A 98.26,28.57 D232.A 98.26,31.11 D233.A 98.26,33.65 D234.A 98.26,36.19 D235.A 98.26,38.73 D236.A 98.26,41.27 D237.A 98.26,43.81 D238.A 98.26,46.35 D239.A 98.26,48.89 D240.A 96.99,61.59 IC4.3
N$2
  Top 0.61: D242.C 98.26,13.33 95.72,13.33 D226.C 93.18,13.33 90.64,13.33 D210.C 88.1,13.33 85.56,13.33 D194.C 83.02,13.33 80.48,13.33 D178.C 77.94,13.33 75.4,13.33 D162.C 72.86,13.33 70.32,13.33 D146.C 67.78,13.33 65.24,13.33 D130.C 62.7,13.33 60.16,13.33 D114.C 57.62,13.33 55.08,13.33 D98.C 52.54,13.33 50,13.33 D82.C 47.46,13.33 44.92,13.33 D66.C 42.38,13.33 39.84,13.33 D50.C 37.3,13.33 34.76,13.33 D34.C 32.22,13.33 29.68,13.33 D18.C 27.14,13.33 24.6,13.33 D2.C
  Bottom 0.61: IC1.2 D2.C
N$3
  Bottom 0.61: R3.1 D33.A 37.3,13.33 D34.A 37.3,15.87 D35.A 37.3,18.41 D36.A 37.3,20.95 D37.A 37.3,23.49 D38.A 37.3,26.03 D39.A 37.3,28.57 D40.A 37.3,31.11 D41.A 37.3,33.65 D42.A 37.3,36.19 D43.A 37.3,38.73 D44.A 37.3,41.27 D45.A 37.3,43.81 D46.A 37.3,46.35 D47.A 37.3,48.89 D48.A 36.03,61.59 IC2.3
N$4
  Top 0.61: D244.C 98.26,18.41 95.72,18.41 D228.C 93.18,18.41 90.64,18.41 D212.C 88.1,18.41 85.56,18.41 D196.C 83.02,18.41 80.48,18.41 D180.C 77.94,18.41 75.4,18.41 D164.C 72.86,18.41 70.32,18.41 D148.C 67.78,18.41 65.24,18.41 D132.C 62.7,18.41 60.16,18.41 D116.C 57.62,18.41 55.08,18.41 D100.C 52.54,18.41 50,18.41 D84.C 47.46,18.41 44.92,18.41 D68.C 42.38,18.41 39.84,18.41 D52.C 37.3,18.41 34.76,18.41 D36.C 32.22,18.41 29.68,18.41 D20.C 27.14,18.41 24.6,18.41 D4.C
  Bottom 0.61: IC1.4 D4.C
N$5
  Top 0.61: D245.C 98.26,20.95 95.72,20.95 D229.C 93.18,20.95 90.64,20.95 D213.C 88.1,20.95 85.56,20.95 D197.C 83.02,20.95 80.48,20.95 D181.C 77.94,20.95 75.4,20.95 D165.C 72.86,20.95 70.32,20.95 D149.C 67.78,20.95 65.24,20.95 D133.C 62.7,20.95 60.16,20.95 D117.C 57.62,20.95 55.08,20.95 D101.C 52.54,20.95 50,20.95 D85.C 47.46,20.95 44.92,20.95 D69.C 42.38,20.95 39.84,20.95 D53.C 37.3,20.95 34.76,20.95 D37.C 32.22,20.95 29.68,20.95 D21.C 27.14,20.95 24.6,20.95 D5.C
  Bottom 0.61: D5.C IC1.5
N$6
  Top 0.61: D246.C 98.26,23.49 95.72,23.49 D230.C 93.18,23.49 90.64,23.49 D214.C 88.1,23.49 85.56,23.49 D198.C 83.02,23.49 80.48,23.49 D182.C 77.94,23.49 75.4,23.49 D166.C 72.86,23.49 70.32,23.49 D150.C 67.78,23.49 65.24,23.49 D134.C 62.7,23.49 60.16,23.49 D118.C 57.62,23.49 55.08,23.49 D102.C 52.54,23.49 50,23.49 D86.C 47.46,23.49 44.92,23.49 D70.C 42.38,23.49 39.84,23.49 D54.C 37.3,23.49 34.76,23.49 D38.C 32.22,23.49 29.68,23.49 D22.C 27.14,23.49 24.6,23.49 D6.C
  Bottom 0.61: IC1.6 D6.C
N$7
  Top 0.61: D247.C 98.26,26.03 95.72,26.03 D231.C 93.18,26.03 90.64,26.03 D215.C 88.1,26.03 85.56,26.03 D199.C 83.02,26.03 80.48,26.03 D183.C 77.94,26.03 75.4,26.03 D167.C 72.86,26.03 70.32,26.03 D151.C 67.78,26.03 65.24,26.03 D135.C 62.7,26.03 60.16,26.03 D119.C 57.62,26.03 55.08,26.03 D103.C 52.54,26.03 50,26.03 D87.C 47.46,26.03 44.92,26.03 D71.C 42.38,26.03 39.84,26.03 D55.C 37.3,26.03 34.76,26.03 D39.C 32.22,26.03 29.68,26.03 D23.C 27.14,26.03 24.6,26.03 D7.C
  Bottom 0.61: D7.C IC1.7
N$8
  Top 0.61: D248.C 98.26,28.57 95.72,28.57 D232.C 93.18,28.57 90.64,28.57 D216.C 88.1,28.57 85.56,28.57 D200.C 83.02,28.57 80.48,28.57 D184.C 77.94,28.57 75.4,28.57 D168.C 72.86,28.57 70.32,28.57 D152.C 67.78,28.57 65.24,28.57 D136.C 62.7,28.57 60.16,28.57 D120.C 57.62,28.57 55.08,28.57 D104.C 52.54,28.57 50,28.57 D88.C 47.46,28.57 44.92,28.57 D72.C 42.38,28.57 39.84,28.57 D56.C 37.3,28.57 34.76,28.57 D40.C 32.22,28.57 29.68,28.57 D24.C 27.14,28.57 24.6,28.57 D8.C
  Bottom 0.61: IC1.8 D8.C
N$9
  Top 0.61: D249.C 98.26,31.11 95.72,31.11 D233.C 93.18,31.11 90.64,31.11 D217.C 88.1,31.11 85.56,31.11 D201.C 83.02,31.11 80.48,31.11 D185.C 77.94,31.11 75.4,31.11 D169.C 72.86,31.11 70.32,31.11 D153.C 67.78,31.11 65.24,31.11 D137.C 62.7,31.11 60.16,31.11 D121.C 57.62,31.11 55.08,31.11 D105.C 52.54,31.11 50,31.11 D89.C 47.46,31.11 44.92,31.11 D73.C 42.38,31.11 39.84,31.11 D57.C 37.3,31.11 34.76,31.11 D41.C 32.22,31.11 29.68,31.11 D25.C 27.14,31.11 24.6,31.11 D9.C
  Bottom 0.61: D9.C IC1.9
N$10
  Top 0.61: D250.C 98.26,33.65 95.72,33.65 D234.C 93.18,33.65 90.64,33.65 D218.C 88.1,33.65 85.56,33.65 D202.C 83.02,33.65 80.48,33.65 D186.C 77.94,33.65 75.4,33.65 D170.C 72.86,33.65 70.32,33.65 D154.C 67.78,33.65 65.24,33.65 D138.C 62.7,33.65 60.16,33.65 D122.C 57.62,33.65 55.08,33.65 D106.C 52.54,33.65 50,33.65 D90.C 47.46,33.65 44.92,33.65 D74.C 42.38,33.65 39.84,33.65 D58.C 37.3,33.65 34.76,33.65 D42.C 32.22,33.65 29.68,33.65 D26.C 27.14,33.65 24.6,33.65 D10.C
  Bottom 0.61: D10.C IC1.10
N$11
  Top 0.61: D251.C 98.26,36.19 95.72,36.19 D235.C 93.18,36.19 90.64,36.19 D219.C 88.1,36.19 85.56,36.19 D203.C 83.02,36.19 80.48,36.19 D187.C 77.94,36.19 75.4,36.19 D171.C 72.86,36.19 70.32,36.19 D155.C 67.78,36.19 65.24,36.19 D139.C 62.7,36.19 60.16,36.19 D123.C 57.62,36.19 55.08,36.19 D107.C 52.54,36.19 50,36.19 D91.C 47.46,36.19 44.92,36.19 D75.C 42.38,36.19 39.84,36.19 D59.C 37.3,36.19 34.76,36.19 D43.C 32.22,36.19 29.68,36.19 D27.C 27.14,36.19 24.6,36.19 D11.C
  Bottom 0.61: D11.C IC1.11
N$12
  Top 0.61: D252.C 98.26,38.73 95.72,38.73 D236.C 93.18,38.73 90.64,38.73 D220.C 88.1,38.73 85.56,38.73 D204.C 83.02,38.73 80.48,38.73 D188.C 77.94,38.73 75.4,38.73 D172.C 72.86,38.73 70.32,38.73 D156.C 67.78,38.73 65.24,38.73 D140.C 62.7,38.73 60.16,38.73 D124.C 57.62,38.73 55.08,38.73 D108.C 52.54,38.73 50,38.73 D92.C 47.46,38.73 44.92,38.73 D76.C 42.38,38.73 39.84,38.73 D60.C 37.3,38.73 34.76,38.73 D44.C 32.22,38.73 29.68,38.73 D28.C 27.14,38.73 24.6,38.73 D12.C
  Bottom 0.61: D12.C 22.06,40 20.79,41.27 11.9,41.27 10.63,40 IC1.13
N$13  (via drill 0.61)
  Top 0.61: D253.C 98.26,41.27 95.72,41.27 D237.C 93.18,41.27 90.64,41.27 D221.C 88.1,41.27 85.56,41.27 D205.C 83.02,41.27 80.48,41.27 D189.C 77.94,41.27 75.4,41.27 D173.C 72.86,41.27 70.32,41.27 D157.C 67.78,41.27 65.24,41.27 D141.C 62.7,41.27 60.16,41.27 D125.C 57.62,41.27 55.08,41.27 D109.C 52.54,41.27 50,41.27 D93.C 47.46,41.27 44.92,41.27 D77.C 42.38,41.27 39.84,41.27 D61.C 37.3,41.27 34.76,41.27 D45.C 32.22,41.27 29.68,41.27 D29.C 27.14,41.27 24.6,41.27 D13.C | v9.36,42.54 v9.36,37.46
  Bottom 0.61: v9.36,42.54 D13.C | IC1.14 v9.36,37.46
N$14  (via drill 0.61)
  Top 0.61: D254.C 98.26,43.81 95.72,43.81 D238.C 93.18,43.81 90.64,43.81 D222.C 88.1,43.81 85.56,43.81 D206.C 83.02,43.81 80.48,43.81 D190.C 77.94,43.81 75.4,43.81 D174.C 72.86,43.81 70.32,43.81 D158.C 67.78,43.81 65.24,43.81 D142.C 62.7,43.81 60.16,43.81 D126.C 57.62,43.81 55.08,43.81 D110.C 52.54,43.81 50,43.81 D94.C 47.46,43.81 44.92,43.81 D78.C 42.38,43.81 39.84,43.81 D62.C 37.3,43.81 34.76,43.81 D46.C 32.22,43.81 29.68,43.81 D30.C 27.14,43.81 24.6,43.81 D14.C | v8.09,45.08 v8.09,34.92
  Bottom 0.61: v8.09,45.08 D14.C | IC1.15 v8.09,34.92
N$15  (via drill 0.61)
  Top 0.61: D255.C 98.26,46.35 95.72,46.35 D239.C 93.18,46.35 90.64,46.35 D223.C 88.1,46.35 85.56,46.35 D207.C 83.02,46.35 80.48,46.35 D191.C 77.94,46.35 75.4,46.35 D175.C 72.86,46.35 70.32,46.35 D159.C 67.78,46.35 65.24,46.35 D143.C 62.7,46.35 60.16,46.35 D127.C 57.62,46.35 55.08,46.35 D111.C 52.54,46.35 50,46.35 D95.C 47.46,46.35 44.92,46.35 D79.C 42.38,46.35 39.84,46.35 D63.C 37.3,46.35 34.76,46.35 D47.C 32.22,46.35 29.68,46.35 D31.C 27.14,46.35 24.6,46.35 D15.C | v6.82,47.62 v6.82,32.38
  Bottom 0.61: v6.82,47.62 D15.C | IC1.16 v6.82,32.38
N$16  (via drill 0.61)
  Top 0.61: D256.C 98.26,48.89 95.72,48.89 D240.C 93.18,48.89 90.64,48.89 D224.C 88.1,48.89 85.56,48.89 D208.C 83.02,48.89 80.48,48.89 D192.C 77.94,48.89 75.4,48.89 D176.C 72.86,48.89 70.32,48.89 D160.C 67.78,48.89 65.24,48.89 D144.C 62.7,48.89 60.16,48.89 D128.C 57.62,48.89 55.08,48.89 D112.C 52.54,48.89 50,48.89 D96.C 47.46,48.89 44.92,48.89 D80.C 42.38,48.89 39.84,48.89 D64.C 37.3,48.89 34.76,48.89 D48.C 32.22,48.89 29.68,48.89 D32.C 27.14,48.89 24.6,48.89 D16.C | v5.55,50.16 v5.55,29.84
  Bottom 0.61: v5.55,50.16 D16.C | IC1.17 v5.55,29.84
N$17
  Bottom 0.61: R4.1 D49.A 42.38,13.33 D50.A 42.38,15.87 D51.A 42.38,18.41 D52.A 42.38,20.95 D53.A 42.38,23.49 D54.A 42.38,26.03 D55.A 42.38,28.57 D56.A 42.38,31.11 D57.A 42.38,33.65 D58.A 42.38,36.19 D59.A 42.38,38.73 D60.A 42.38,41.27 D61.A 42.38,43.81 D62.A 42.38,46.35 D63.A 42.38,48.89 D64.A 41.11,66.67 IC2.5
N$18
  Bottom 0.61: R5.1 D65.A 47.46,13.33 D66.A 47.46,15.87 D67.A 47.46,18.41 D68.A 47.46,20.95 D69.A 47.46,23.49 D70.A 47.46,26.03 D71.A 47.46,28.57 D72.A 47.46,31.11 D73.A 47.46,33.65 D74.A 47.46,36.19 D75.A 47.46,38.73 D76.A 47.46,41.27 D77.A 47.46,43.81 D78.A 47.46,46.35 D79.A 47.46,48.89 D80.A 46.19,69.21 IC3.9
N$19
  Bottom 0.61: R6.1 D81.A 52.54,13.33 D82.A 52.54,15.87 D83.A 52.54,18.41 D84.A 52.54,20.95 D85.A 52.54,23.49 D86.A 52.54,26.03 D87.A 52.54,28.57 D88.A 52.54,31.11 D89.A 52.54,33.65 D90.A 52.54,36.19 D91.A 52.54,38.73 D92.A 52.54,41.27 D93.A 52.54,43.81 D94.A 52.54,46.35 D95.A 52.54,48.89 D96.A 51.27,64.13 IC3.11
N$20
  Bottom 0.61: R7.1 D97.A 57.62,13.33 D98.A 57.62,15.87 D99.A 57.62,18.41 D100.A 57.62,20.95 D101.A 57.62,23.49 D102.A 57.62,26.03 D103.A 57.62,28.57 D104.A 57.62,31.11 D105.A 57.62,33.65 D106.A 57.62,36.19 D107.A 57.62,38.73 D108.A 57.62,41.27 D109.A 57.62,43.81 D110.A 57.62,46.35 D111.A 57.62,48.89 D112.A 56.35,59.05 IC3.13
N$21
  Top 0.61: D243.C 98.26,15.87 95.72,15.87 D227.C 93.18,15.87 90.64,15.87 D211.C 88.1,15.87 85.56,15.87 D195.C 83.02,15.87 80.48,15.87 D179.C 77.94,15.87 75.4,15.87 D163.C 72.86,15.87 70.32,15.87 D147.C 67.78,15.87 65.24,15.87 D131.C 62.7,15.87 60.16,15.87 D115.C 57.62,15.87 55.08,15.87 D99.C 52.54,15.87 50,15.87 D83.C 47.46,15.87 44.92,15.87 D67.C 42.38,15.87 39.84,15.87 D51.C 37.3,15.87 34.76,15.87 D35.C 32.22,15.87 29.68,15.87 D19.C 27.14,15.87 24.6,15.87 D3.C
  Bottom 0.61: D3.C IC1.3
N$22  (via drill 0.61)
  Top 0.61: v11.9,24.76 v11.9,51.43
  Bottom 0.61: IC1.19 v11.9,24.76 11.9,14.6 RN1.6 JP1.6 | IC2.11 11.9,64.13 v11.9,51.43
N$23  (via drill 0.61)
  Top 0.61: v14.44,27.3 v14.44,51.43
  Bottom 0.61: JP1.7 RN1.7 14.44,13.33 v14.44,27.3 IC1.18 | v14.44,51.43 14.44,59.05 IC2.13
N$24
  Bottom 0.61: R10.1 D145.A 72.86,13.33 D146.A 72.86,15.87 D147.A 72.86,18.41 D148.A 72.86,20.95 D149.A 72.86,23.49 D150.A 72.86,26.03 D151.A 72.86,28.57 D152.A 72.86,31.11 D153.A 72.86,33.65 D154.A 72.86,36.19 D155.A 72.86,38.73 D156.A 72.86,41.27 D157.A 72.86,43.81 D158.A 72.86,46.35 D159.A 72.86,48.89 D160.A 71.59,66.67 IC3.5
N$25
  Bottom 0.61: R13.1 D193.A 88.1,13.33 D194.A 88.1,15.87 D195.A 88.1,18.41 D196.A 88.1,20.95 D197.A 88.1,23.49 D198.A 88.1,26.03 D199.A 88.1,28.57 D200.A 88.1,31.11 D201.A 88.1,33.65 D202.A 88.1,36.19 D203.A 88.1,38.73 D204.A 88.1,41.27 D205.A 88.1,43.81 D206.A 88.1,46.35 D207.A 88.1,48.89 D208.A 86.83,59.05 IC4.13
N$26
  Bottom 0.61: IC1.23 4.28,14.6 5.55,12.06 RN1.2 JP1.2
N$27
  Bottom 0.61: IC1.22 5.55,17.14 8.09,9.52 RN1.3 JP1.3
N$28
  Bottom 0.61: IC1.21 6.82,19.68 6.82,18.41 10.63,9.52 RN1.4 JP1.4
N$29
  Bottom 0.61: R1.1 D1.A 27.14,13.33 D2.A 27.14,15.87 D3.A 27.14,18.41 D4.A 27.14,20.95 D5.A 27.14,23.49 D6.A 27.14,26.03 D7.A 27.14,28.57 D8.A 27.14,31.11 D9.A 27.14,33.65 D10.A 27.14,36.19 D11.A 27.14,38.73 D12.A 27.14,41.27 D13.A 27.14,43.81 D14.A 27.14,46.35 D15.A 27.14,48.89 D16.A 25.87,69.21 IC2.9
N$30
  Bottom 0.61: R2.1 D17.A 32.22,13.33 D18.A 32.22,15.87 D19.A 32.22,18.41 D20.A 32.22,20.95 D21.A 32.22,23.49 D22.A 32.22,26.03 D23.A 32.22,28.57 D24.A 32.22,31.11 D25.A 32.22,33.65 D26.A 32.22,36.19 D27.A 32.22,38.73 D28.A 32.22,41.27 D29.A 32.22,43.81 D30.A 32.22,46.35 D31.A 32.22,48.89 D32.A IC2.1
N$31
  Bottom 0.61: IC1.20 9.36,22.22 9.36,15.87 13.17,9.52 RN1.5 JP1.5
N$32
  Bottom 0.61: R8.1 D113.A 62.7,13.33 D114.A 62.7,15.87 D115.A 62.7,18.41 D116.A 62.7,20.95 D117.A 62.7,23.49 D118.A 62.7,26.03 D119.A 62.7,28.57 D120.A 62.7,31.11 D121.A 62.7,33.65 D122.A 62.7,36.19 D123.A 62.7,38.73 D124.A 62.7,41.27 D125.A 62.7,43.81 D126.A 62.7,46.35 D127.A 62.7,48.89 D128.A IC3.1
N$33
  Bottom 0.61: R9.1 D129.A 67.78,13.33 D130.A 67.78,15.87 D131.A 67.78,18.41 D132.A 67.78,20.95 D133.A 67.78,23.49 D134.A 67.78,26.03 D135.A 67.78,28.57 D136.A 67.78,31.11 D137.A 67.78,33.65 D138.A 67.78,36.19 D139.A 67.78,38.73 D140.A 67.78,41.27 D141.A 67.78,43.81 D142.A 67.78,46.35 D143.A 67.78,48.89 D144.A 66.51,61.59 IC3.3
N$34
  Bottom 0.61: R16.1 D241.A 103.34,13.33 D242.A 103.34,15.87 D243.A 103.34,18.41 D244.A 103.34,20.95 D245.A 103.34,23.49 D246.A 103.34,26.03 D247.A 103.34,28.57 D248.A 103.34,31.11 D249.A 103.34,33.65 D250.A 103.34,36.19 D251.A 103.34,38.73 D252.A 103.34,41.27 D253.A 103.34,43.81 D254.A 103.34,46.35 D255.A 103.34,48.89 D256.A 102.07,66.67 IC4.5
N$38  (via drill 0.61)
  other vias: 19.52,61.59 19.52,61.59
N$39
  Bottom 0.61: R14.1 D209.A 93.18,13.33 D210.A 93.18,15.87 D211.A 93.18,18.41 D212.A 93.18,20.95 D213.A 93.18,23.49 D214.A 93.18,26.03 D215.A 93.18,28.57 D216.A 93.18,31.11 D217.A 93.18,33.65 D218.A 93.18,36.19 D219.A 93.18,38.73 D220.A 93.18,41.27 D221.A 93.18,43.81 D222.A 93.18,46.35 D223.A 93.18,48.89 D224.A IC4.1
N$40  (via drill 0.61)
  other vias: 36.03,71.75 19.52,61.59 19.52,61.59 14.44,27.3 11.9,24.76 19.52,61.59
N$41
  Bottom 0.61: R11.1 D161.A 77.94,13.33 D162.A 77.94,15.87 D163.A 77.94,18.41 D164.A 77.94,20.95 D165.A 77.94,23.49 D166.A 77.94,26.03 D167.A 77.94,28.57 D168.A 77.94,31.11 D169.A 77.94,33.65 D170.A 77.94,36.19 D171.A 77.94,38.73 D172.A 77.94,41.27 D173.A 77.94,43.81 D174.A 77.94,46.35 D175.A 77.94,48.89 D176.A 76.67,69.21 IC4.9
N$42
  Top 0.61: D1.C 24.6,10.79 27.14,10.79 D17.C 29.68,10.79 32.22,10.79 D33.C 34.76,10.79 37.3,10.79 D49.C 39.84,10.79 42.38,10.79 D65.C 44.92,10.79 47.46,10.79 D81.C 50,10.79 52.54,10.79 D97.C 55.08,10.79 57.62,10.79 D113.C 60.16,10.79 62.7,10.79 D129.C 65.24,10.79 67.78,10.79 D145.C 70.32,10.79 72.86,10.79 D161.C 75.4,10.79 77.94,10.79 D177.C 80.48,10.79 83.02,10.79 D193.C 85.56,10.79 88.1,10.79 D209.C 90.64,10.79 93.18,10.79 D225.C 95.72,10.79 98.26,10.79 D241.C
  Bottom 0.61: IC1.1 D1.C
N$43  (via drill 0.61 pad 2.18)
  other vias: 3.01,53.97
N$44  (via drill 0.61 pad 2.18)
  other vias: 8.09,53.97
N$45  (via drill 0.61 pad 2.54)
  other vias: 43.65,71.75
N$46  (via drill 0.61 pad 2.54)
  other vias: 74.13,71.75
N$47  (via drill 0.61 pad 2.54)
  other vias: 13.17,71.75
N$48  (via drill 0.61 pad 2.54)
  other vias: 43.65,71.75 74.13,71.75 43.65,67.94 74.13,67.94
N$50
  Bottom 0.61: R12.1 D177.A 83.02,13.33 D178.A 83.02,15.87 D179.A 83.02,18.41 D180.A 83.02,20.95 D181.A 83.02,23.49 D182.A 83.02,26.03 D183.A 83.02,28.57 D184.A 83.02,31.11 D185.A 83.02,33.65 D186.A 83.02,36.19 D187.A 83.02,38.73 D188.A 83.02,41.27 D189.A 83.02,43.81 D190.A 83.02,46.35 D191.A 83.02,48.89 D192.A 81.75,64.13 IC4.11
N$51  (via drill 0.61)
  Top 0.61: v19.52,61.59 v19.52,73.02
  Bottom 0.61: IC2.12 v19.52,61.59 | v19.52,73.02 G1.MP
N$52
  Bottom 0.61: IC2.8 23.33,74.29 Q0.MP
N$53  (via drill 0.61)
  Top 0.61: v33.49,59.05 v33.49,71.75
  Bottom 0.61: IC2.2 v33.49,59.05 | v33.49,71.75 Q1.MP
N$54  (via drill 0.61)
  Top 0.61: v36.03,71.75 v36.03,64.13
  Bottom 0.61: IC2.4 v36.03,64.13 | Q2.MP v36.03,71.75
N$55
  Bottom 0.61: IC2.6 38.57,69.21 38.57,73.02 Q3.MP
N$56
  Bottom 0.61: IC3.8 48.73,71.75 48.73,73.02 Q4.MP
N$57  (via drill 0.61)
  Top 0.61: v51.27,66.67 v51.27,73.02
  Bottom 0.61: IC3.10 v51.27,66.67 | v51.27,73.02 Q5.MP
N$58
  Bottom 0.61: IC3.12 56.35,61.59 Q6.MP
N$59  (via drill 0.61)
  Top 0.61: v63.97,59.05 v63.97,73.02
  Bottom 0.61: IC3.2 v63.97,59.05 | v63.97,73.02 Q7.MP
N$60  (via drill 0.61)
  Top 0.61: v66.51,64.13 v66.51,73.02
  Bottom 0.61: IC3.4 v66.51,64.13 | v66.51,73.02 Q8.MP
N$61
  Bottom 0.61: IC3.6 69.05,69.21 69.05,73.02 Q9.MP
N$62
  Bottom 0.61: IC4.8 79.21,71.75 79.21,73.02 Q10.MP
N$63  (via drill 0.61)
  Top 0.61: v81.75,66.67 v81.75,73.02
  Bottom 0.61: IC4.10 v81.75,66.67 | v81.75,73.02 Q11.MP
N$64
  Bottom 0.61: IC4.12 86.83,61.59 Q12.MP
N$65  (via drill 0.61)
  Top 0.61: v94.45,59.05 v94.45,73.02
  Bottom 0.61: IC4.2 v94.45,59.05 | v94.45,73.02 Q13.MP
N$66  (via drill 0.61)
  Top 0.61: v96.99,64.13 v96.99,73.02
  Bottom 0.61: IC4.4 v96.99,64.13 | v96.99,73.02 Q14.MP
N$67
  Bottom 0.61: IC4.6 99.53,69.21 99.53,73.02 Q15.MP
N$68
  Bottom 0.61: IC2.10 16.98,66.67 16.98,73.02 G2.MP
VCC  (via drill 0.61, 0.61 pad 2.54)
  Top 0.813: 43.65,53.97 v43.65,67.94 | 74.13,53.97 v74.13,67.94 | IC4.14 83.02,53.97 74.13,53.97 | 74.13,53.97 55.08,53.97 IC3.14 52.54,53.97 43.65,53.97 | 43.65,53.97 24.6,53.97 IC2.14
  Top 1.016: v3.01,71.75 v13.17,71.75 | IC2.14 5.55,56.51 v3.01,53.97
  Bottom 0.61: R16.2 100.8,1.9 98.26,1.9 R15.2 95.72,1.9 93.18,1.9 R14.2 90.64,1.9 88.1,1.9 R13.2 85.56,1.9 83.02,1.9 R12.2 80.48,1.9 77.94,1.9 R11.2 75.4,1.9 72.86,1.9 R10.2 70.32,1.9 67.78,1.9 R9.2 65.24,1.9 62.7,1.9 R8.2 60.16,1.9 57.62,1.9 R7.2 55.08,1.9 52.54,1.9 R6.2 50,1.9 47.46,1.9 R5.2 44.92,1.9 42.38,1.9 R4.2 39.84,1.9 37.3,1.9 R3.2 34.76,1.9 32.22,1.9 R2.2 29.68,1.9 27.14,1.9 R1.2 | v43.65,67.94 43.65,71.75 | v74.13,67.94 74.13,71.75 | v3.01,71.75 v3.01,67.94
  Bottom 1.016: v3.01,71.75 +5V.MP | v13.17,71.75 +5V3.MP | v3.01,67.94 v3.01,53.97 0.47,51.43 0.47,12.06 0.47,8.25 | 1.74,12.06 IC1.24 | 0.47,8.25 RN1.1 | 0.47,3.17 0.47,8.25 | 0.47,3.17 JP1.1 | 0.47,3.17 0.47,0.63 1.74,0.63 | 3.01,0.63 24.6,0.63 R1.2
  Bottom 1.27: 24.6,0.63 103.34,0.63 103.34,1.9 R16.2 | IC1.24 3.01,0.63 1.74,0.63 1.74,12.06 0.47,12.06 0.47,0.63 | 43.65,71.75 +5V2.MP | 74.13,71.75 +5V1.MP
  Bottom 1.422: 103.34,1.9 25.87,1.9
